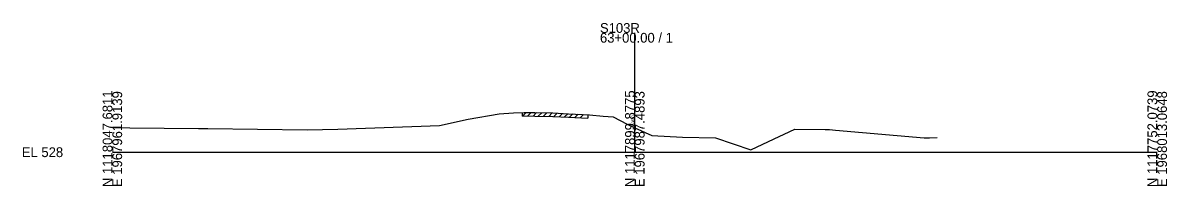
# Model space of a CAD drawing. Extents: x 974 to 1303, y 990 to 10019.
# Drawn here: x 974.3 to 1302.8, y 5490.3 to 5537 of the extents above; entities that cross this region are included whole.
import ezdxf

# ---------------------------------------------------------------- set-up
doc = ezdxf.new("R2010")
doc.units = 0
for name, color, linetype in [('Level 10', 7, 'Continuous'), ('Level 60', 7, 'Continuous'), ('Level 61', 7, 'Continuous'), ('Level 63', 7, 'Continuous')]:
    doc.layers.add(name, color=color, linetype=linetype)

msp = doc.modelspace()

# ---------------------------------------------------------------- linework, layer by layer
at = {"layer": 'Level 60'}
for p, q in [((1102.19, 5509.42), (1111.03, 5511.01)), ((1111.03, 5511.01), (1115.15, 5511.25)), ((1115.15, 5511.25), (1118.27, 5511.39)), ((1118.27, 5511.39), (1121.29, 5511.33)), ((1121.29, 5511.33), (1126.5, 5511.23)), ((1126.5, 5511.23), (1130.93, 5511.02)), ((1130.93, 5511.02), (1136.98, 5510.69)), ((1136.98, 5510.69), (1140.91, 5510.35)), ((1140.91, 5510.35), (1143.79, 5510.08)), ((1143.79, 5510.08), (1147.84, 5508.01)), ((1000, 5507.1), (1005.02, 5507)), ((1005.02, 5507), (1024.69, 5506.8)), ((1024.69, 5506.8), (1027.37, 5506.76)), ((1027.37, 5506.76), (1055.9, 5506.39)), ((1055.9, 5506.39), (1064.71, 5506.62)), ((1064.71, 5506.62), (1093.89, 5507.66)), ((1093.89, 5507.66), (1102.19, 5509.42)), ((1147.84, 5508.01), (1150, 5507.01)), ((1150, 5507.01), (1154.85, 5504.76)), ((1188.38, 5503.1), (1195.94, 5506.56)), ((1195.94, 5506.56), (1204.62, 5506.46)), ((1204.62, 5506.46), (1205.94, 5506.48)), ((1205.94, 5506.48), (1207.59, 5506.32)), ((1207.59, 5506.32), (1233.05, 5504.1)), ((1154.85, 5504.76), (1163.68, 5504.27)), ((1163.68, 5504.27), (1173.18, 5504.15)), ((1173.18, 5504.15), (1178.28, 5502.44)), ((1183.28, 5500.69), (1188.38, 5503.1)), ((1233.05, 5504.1), (1234.62, 5504.15)), ((1234.62, 5504.15), (1236.83, 5504.16)), ((1178.28, 5502.44), (1183.28, 5500.69))]:
    msp.add_line(p, q, dxfattribs=at)
at = {"layer": 'Level 61'}
for p, q in [((1117.79, 5510.36), (1118.8, 5511.38)), ((1117.79, 5510.36), (1117.79, 5511.36)), ((1117.79, 5510.36), (1118.27, 5510.39)), ((1118.27, 5510.39), (1121.29, 5510.33)), ((1119.29, 5510.37), (1120.27, 5511.35)), ((1120.79, 5510.34), (1121.77, 5511.32)), ((1121.29, 5510.33), (1126.5, 5510.23)), ((1122.29, 5510.31), (1123.27, 5511.29)), ((1123.79, 5510.28), (1124.77, 5511.26)), ((1125.29, 5510.25), (1126.27, 5511.23)), ((1126.5, 5510.23), (1130.93, 5510.02)), ((1126.79, 5510.22), (1127.74, 5511.17)), ((1128.29, 5510.15), (1129.24, 5511.1)), ((1129.79, 5510.08), (1130.74, 5511.03)), ((1130.93, 5510.02), (1136.52, 5509.72)), ((1131.29, 5510), (1132.24, 5510.95)), ((1132.79, 5509.92), (1133.74, 5510.87)), ((1134.29, 5509.84), (1135.24, 5510.79)), ((1136.52, 5510.72), (1136.52, 5509.72))]:
    msp.add_line(p, q, dxfattribs=at)
at = {"layer": 'Level 63'}
for p, q in [((1150, 5500), (1150, 5534.16)), ((1000, 5500), (1150, 5500)), ((1150, 5500), (1300, 5500))]:
    msp.add_line(p, q, dxfattribs=at)

# ---------------------------------------------------------------- texts
at = {"layer": 'Level 10'}
msp.add_text('535.01', height=0.9, rotation=90, dxfattribs=at).set_placement((1149.95, 5507.51))
at = {"layer": 'Level 63'}
for s, p in [('S103R', (1140, 5534.16)), ('63+00.00 / 1', (1140, 5531.36)), ('EL 528', (974, 5498.6))]:
    msp.add_text(s, height=2.8, dxfattribs=at).set_placement(p)
for s, p in [('N 1118047.6811', (1000, 5490)), ('E 1967961.9139', (1002.8, 5490)), ('N 1117899.8775', (1150, 5490)), ('E 1967987.4893', (1152.8, 5490)), ('N 1117752.0739', (1300, 5490)), ('E 1968013.0648', (1302.8, 5490))]:
    msp.add_text(s, height=2.8, rotation=90, dxfattribs=at).set_placement(p)

doc.saveas('drawing.dxf')
